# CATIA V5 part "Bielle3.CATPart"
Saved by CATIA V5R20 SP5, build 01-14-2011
Part number: Bielle3
Bounding box of the stored display mesh (mm): x 0 to 50, y -117.061 to 21.684, z -0.806 to 19.189
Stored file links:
  U:\IAO_projet\Bielle3.CATPart
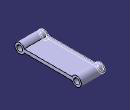
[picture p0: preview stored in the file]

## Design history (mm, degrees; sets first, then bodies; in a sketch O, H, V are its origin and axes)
Body1 (main body)
  Sketch1 on yz-plane, origin (0, 0, 0), H (0, 1, 0), V (0, 0, 1)
    line L1 (-97.6882, 12.6779) -> (2.3118, 12.6779)
    line L2 (2.3118, 5.705) -> (-97.6882, 5.705)
    arc A1 centre (11.6843, 9.1915) radius 10 from (2.3118, 12.6779) to (2.3118, 5.705) cw
    arc A2 centre (-107.0608, 9.1915) radius 10 from (-97.6882, 12.6779) to (-97.6882, 5.705) ccw
    point P7 (-111, 0)
    circle A3 centre (11.6843, 9.1915) radius 6
    circle A4 centre (-107.0608, 9.1915) radius 6
    radius A2 = 10
    length L1 = 100
    length L2 = 100
    horizontal: L1 H, L2 H
    coincidence: A2 P7, P7 H
  Pad1: profile Sketch1, direction (1, 0, 0), length 50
